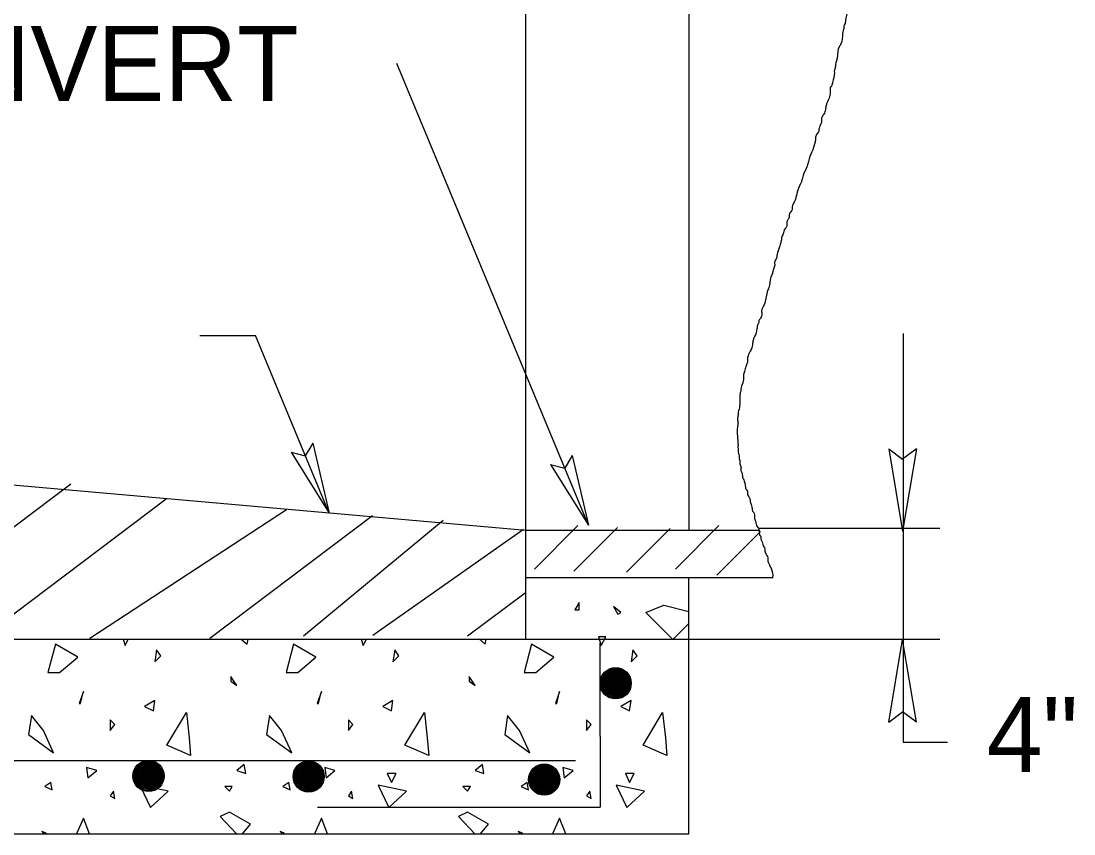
# Model space of a CAD drawing. Extents: x 5.8 to 18, y -5.2 to 5.4.
# Drawn here: x 12.113 to 12.953, y -2.199 to -1.55 of the extents above; entities that cross this region are included whole.
import ezdxf

# ---------------------------------------------------------------- set-up
doc = ezdxf.new("R2010")
doc.units = 0
for name, color, linetype in [('DETL-DIMS', 7, 'Continuous'), ('DETL-LINE', 7, 'Continuous'), ('DETL-NOTE', 7, 'Continuous'), ('DETL-PATT', 7, 'Continuous')]:
    doc.layers.add(name, color=color, linetype=linetype)

msp = doc.modelspace()

# ---------------------------------------------------------------- linework, layer by layer
at = {"layer": 'DETL-DIMS'}
for p, q in [((12.566, -1.95226), (12.41306, -1.58371)), ((12.2558, -1.80088), (12.3002, -1.80088)), ((12.35898, -1.94253), (12.3002, -1.80088)), ((12.81726, -1.7993), (12.81726, -2.12544)), ((12.34604, -1.88677), (12.34004, -1.89688)), ((12.34604, -1.88677), (12.35898, -1.94253)), ((12.32867, -1.89398), (12.35898, -1.94253)), ((12.32867, -1.89398), (12.34004, -1.89688)), ((12.55306, -1.89649), (12.54706, -1.90661)), ((12.55306, -1.89649), (12.566, -1.95226)), ((12.80576, -1.8913), (12.81674, -1.95718)), ((12.80576, -1.8913), (12.81674, -1.89953)), ((12.82772, -1.8913), (12.81674, -1.95718)), ((12.82772, -1.8913), (12.81674, -1.89953)), ((12.53569, -1.90371), (12.566, -1.95226)), ((12.53569, -1.90371), (12.54706, -1.90661)), ((12.70169, -1.95465), (12.84634, -1.95465)), ((12.51612, -2.04328), (12.84634, -2.04328)), ((12.80576, -2.10927), (12.81674, -2.04339)), ((12.82772, -2.10927), (12.81674, -2.04339)), ((12.80576, -2.10927), (12.81674, -2.10103)), ((12.82772, -2.10927), (12.81674, -2.10103)), ((12.81726, -2.12544), (12.85257, -2.12544))]:
    msp.add_line(p, q, dxfattribs=at)
at = {"layer": 'DETL-LINE'}
for p, q in [((12.51612, -2.04328), (12.51612, -0.81414)), ((12.646, -1.47622), (12.646, -1.95618)), ((12.51612, -1.95637), (11.58024, -1.87386)), ((12.51667, -1.95618), (12.70208, -1.95618)), ((12.51639, -1.9939), (12.71329, -1.9939)), ((12.646, -2.19861), (12.646, -1.9939)), ((11.5809, -2.04328), (12.51612, -2.04328)), ((12.57525, -2.12069), (12.57525, -2.04645)), ((12.57525, -2.12069), (12.57525, -2.17712)), ((11.53804, -2.1399), (12.55565, -2.1399)), ((12.34969, -2.17712), (12.57525, -2.17712)), ((11.45961, -2.19861), (12.646, -2.19861))]:
    msp.add_line(p, q, dxfattribs=at)
for centre, radius in [((12.58772, -2.07837), 0.01247), ((12.58761, -2.07827), 0.01163), ((12.5865, -2.07827), 0.01009), ((12.58775, -2.07856), 0.01122), ((12.58808, -2.07909), 0.011), ((12.58803, -2.0787), 0.01024), ((12.58691, -2.07778), 0.00834), ((12.5883, -2.07876), 0.00969), ((12.58838, -2.07903), 0.00918), ((12.58671, -2.07876), 0.00724), ((12.58852, -2.07917), 0.00876), ((12.58838, -2.07939), 0.00835), ((12.58608, -2.07917), 0.00578), ((12.58859, -2.07939), 0.00814), ((12.58844, -2.07925), 0.00786), ((12.58879, -2.07945), 0.00751), ((12.58887, -2.07931), 0.00704), ((12.58705, -2.0789), 0.00467), ((12.58893, -2.07923), 0.00655), ((12.58893, -2.07909), 0.006), ((12.58901, -2.07925), 0.00565), ((12.58901, -2.07931), 0.0051), ((12.58922, -2.07974), 0.00488), ((12.58934, -2.0798), 0.00445), ((12.58934, -2.07968), 0.0039), ((12.5895, -2.07958), 0.00377), ((12.5895, -2.07994), 0.00347), ((12.58963, -2.07966), 0.00333), ((12.58969, -2.07974), 0.00285), ((12.5895, -2.07952), 0.00238), ((12.58977, -2.07982), 0.00212), ((12.58985, -2.0798), 0.00175), ((12.58999, -2.07988), 0.00133), ((12.58999, -2.07974), 0.00118), ((12.5904, -2.0798), 0.00148), ((12.58997, -2.07974), 0.000769), ((12.58983, -2.07974), 0.000362), ((12.59012, -2.07974), 0.00023), ((12.21498, -2.15237), 0.01247), ((12.21487, -2.15227), 0.01163), ((12.21376, -2.15227), 0.01009), ((12.21501, -2.15256), 0.01122), ((12.21534, -2.15309), 0.011), ((12.21529, -2.1527), 0.01024), ((12.34271, -2.15281), 0.01247), ((12.34261, -2.15271), 0.01163), ((12.34275, -2.153), 0.01122), ((12.34308, -2.15353), 0.011), ((12.21417, -2.15178), 0.00834), ((12.21556, -2.15276), 0.00969), ((12.21564, -2.15303), 0.00918), ((12.21397, -2.15276), 0.00724), ((12.21578, -2.15317), 0.00876), ((12.21564, -2.15338), 0.00835), ((12.21334, -2.15317), 0.00578), ((12.21585, -2.15338), 0.00814), ((12.2157, -2.15325), 0.00786), ((12.21605, -2.15344), 0.00751), ((12.21613, -2.1533), 0.00704), ((12.21431, -2.15289), 0.00467), ((12.21619, -2.15323), 0.00655), ((12.21619, -2.15309), 0.006), ((12.21627, -2.15325), 0.00565), ((12.21627, -2.1533), 0.0051), ((12.21648, -2.15374), 0.00488), ((12.2166, -2.15379), 0.00445), ((12.2166, -2.15368), 0.0039), ((12.21676, -2.15358), 0.00377), ((12.21676, -2.15393), 0.00347), ((12.21689, -2.15366), 0.00333), ((12.21695, -2.15374), 0.00285), ((12.34149, -2.15271), 0.01009), ((12.34302, -2.15314), 0.01024), ((12.3419, -2.15222), 0.00834), ((12.34329, -2.1532), 0.00969), ((12.34337, -2.15347), 0.00918), ((12.34171, -2.1532), 0.00724), ((12.34351, -2.15361), 0.00876), ((12.34337, -2.15383), 0.00835), ((12.34108, -2.15361), 0.00578), ((12.34359, -2.15383), 0.00814), ((12.34343, -2.15369), 0.00786), ((12.34378, -2.15388), 0.00751), ((12.34386, -2.15375), 0.00704), ((12.34392, -2.15367), 0.00655), ((12.34204, -2.15334), 0.00467), ((12.34392, -2.15353), 0.006), ((12.344, -2.15369), 0.00565), ((12.344, -2.15375), 0.0051), ((12.34422, -2.15418), 0.00488), ((12.34433, -2.15424), 0.00445), ((12.34433, -2.15412), 0.0039), ((12.34449, -2.15402), 0.00377), ((12.34449, -2.15437), 0.00347), ((12.34463, -2.1541), 0.00333), ((12.53068, -2.15524), 0.01247), ((12.53057, -2.15514), 0.01163), ((12.52945, -2.15514), 0.01009), ((12.53071, -2.15543), 0.01122), ((12.53104, -2.15596), 0.011), ((12.53098, -2.15557), 0.01024), ((12.52986, -2.15465), 0.00834), ((12.53125, -2.15563), 0.00969), ((12.53133, -2.1559), 0.00918), ((12.52967, -2.15563), 0.00724), ((12.53147, -2.15604), 0.00876), ((12.53133, -2.15626), 0.00835), ((12.52904, -2.15604), 0.00578), ((12.53155, -2.15626), 0.00814), ((12.53139, -2.15612), 0.00786), ((12.53175, -2.15632), 0.00751), ((12.53182, -2.15618), 0.00704), ((12.53188, -2.1561), 0.00655), ((12.53188, -2.15596), 0.006), ((12.53196, -2.15612), 0.00565), ((12.21676, -2.15352), 0.00238), ((12.21703, -2.15381), 0.00212), ((12.21711, -2.15379), 0.00175), ((12.21725, -2.15387), 0.00133), ((12.21725, -2.15374), 0.00118), ((12.21766, -2.15379), 0.00148), ((12.21723, -2.15374), 0.000769), ((12.21709, -2.15374), 0.000362), ((12.21738, -2.15374), 0.00023), ((12.34469, -2.15418), 0.00285), ((12.34449, -2.15396), 0.00238), ((12.34476, -2.15426), 0.00212), ((12.34484, -2.15424), 0.00175), ((12.34498, -2.15432), 0.00133), ((12.34498, -2.15418), 0.00118), ((12.34539, -2.15424), 0.00148), ((12.34496, -2.15418), 0.000769), ((12.34482, -2.15418), 0.000362), ((12.34512, -2.15418), 0.00023), ((12.53, -2.15577), 0.00467), ((12.53196, -2.15618), 0.0051), ((12.53218, -2.15661), 0.00488), ((12.53229, -2.15667), 0.00445), ((12.53229, -2.15655), 0.0039), ((12.53245, -2.15645), 0.00377), ((12.53245, -2.15681), 0.00347), ((12.53259, -2.15653), 0.00333), ((12.53265, -2.15661), 0.00285), ((12.53245, -2.15639), 0.00238), ((12.53273, -2.15669), 0.00212), ((12.5328, -2.15667), 0.00175), ((12.53294, -2.15675), 0.00133), ((12.53294, -2.15661), 0.00118), ((12.53335, -2.15667), 0.00148), ((12.53292, -2.15661), 0.000769), ((12.53278, -2.15661), 0.000362), ((12.53308, -2.15661), 0.00023)]:
    msp.add_circle(centre, radius, dxfattribs=at)
msp.add_arc((12.70085, -1.99271), 0.01247, 354.49539, 26.62684, dxfattribs=at)
for points in [[(12.76761, -1.45041), (12.76714, -1.4523), (12.76761, -1.45371), (12.76757, -1.45512), (12.76804, -1.45653), (12.76804, -1.45794), (12.76851, -1.45983), (12.76898, -1.46218), (12.76898, -1.46406), (12.76992, -1.46547), (12.76992, -1.46735), (12.77086, -1.47065), (12.77086, -1.47347), (12.7718, -1.47818), (12.77176, -1.48053), (12.77271, -1.48288), (12.77271, -1.48524), (12.77318, -1.489), (12.77318, -1.49041), (12.77412, -1.49653), (12.77412, -1.5003), (12.77459, -1.50312), (12.77455, -1.51347), (12.77502, -1.51583), (12.77455, -1.51822), (12.77455, -1.52198), (12.77408, -1.52481), (12.77408, -1.53139), (12.77314, -1.53563), (12.77314, -1.53751), (12.77267, -1.53939), (12.77263, -1.54081), (12.77216, -1.54269), (12.77216, -1.5441), (12.77169, -1.54645), (12.77122, -1.54881), (12.77075, -1.55163), (12.7698, -1.55351), (12.7698, -1.55586), (12.76933, -1.55728), (12.76886, -1.55963), (12.76745, -1.5681), (12.76604, -1.57045), (12.76463, -1.57798), (12.76416, -1.58081), (12.76322, -1.5841), (12.76275, -1.58739), (12.76227, -1.58881), (12.76224, -1.59116), (12.76082, -1.59873), (12.75988, -1.60155), (12.75894, -1.60296), (12.75894, -1.60532), (12.75659, -1.61473), (12.75565, -1.61708), (12.75518, -1.62037), (12.75376, -1.62414), (12.75235, -1.62649), (12.75188, -1.62837), (12.75188, -1.63073), (12.75, -1.63543), (12.74953, -1.63826), (12.74765, -1.64108), (12.74718, -1.6439), (12.74671, -1.6472), (12.74431, -1.65426), (12.74149, -1.66179), (12.74055, -1.66555), (12.73725, -1.67308), (12.73631, -1.67688), (12.73537, -1.67924), (12.73443, -1.68112), (12.73302, -1.68488), (12.73161, -1.69053), (12.73067, -1.69335), (12.72878, -1.69712), (12.72831, -1.70088), (12.72643, -1.70371), (12.72596, -1.707), (12.72455, -1.70935), (12.72408, -1.71406), (12.7222, -1.71641), (12.72173, -1.71877), (12.72031, -1.72206), (12.71984, -1.72535), (12.7189, -1.72818), (12.71843, -1.73006), (12.71651, -1.73618), (12.71604, -1.739), (12.71463, -1.74183), (12.71463, -1.74465), (12.71369, -1.74794), (12.71275, -1.75124), (12.71133, -1.75504), (12.71086, -1.75786), (12.70992, -1.76257), (12.70851, -1.76586)], [(12.70851, -1.76586), (12.7071, -1.77339), (12.70616, -1.77622), (12.70522, -1.7781), (12.70427, -1.78045), (12.70427, -1.78328), (12.70333, -1.78704), (12.70192, -1.78892), (12.70192, -1.79034), (12.70098, -1.79269), (12.70047, -1.79551), (12.69859, -1.80163), (12.69765, -1.80351), (12.69718, -1.80539), (12.69671, -1.80916), (12.69435, -1.81481), (12.69294, -1.81951), (12.69294, -1.82234), (12.692, -1.82422), (12.69153, -1.82563), (12.69059, -1.82939), (12.68965, -1.83273), (12.68965, -1.83602), (12.68824, -1.8412), (12.68729, -1.8459), (12.68682, -1.84873), (12.68678, -1.85014), (12.68584, -1.86096), (12.68537, -1.86285), (12.68537, -1.86426), (12.6849, -1.86755), (12.68537, -1.87085), (12.6849, -1.87367), (12.6849, -1.8812), (12.68533, -1.88685), (12.68533, -1.89014), (12.6858, -1.89485), (12.68627, -1.89673), (12.68627, -1.89908), (12.68675, -1.90049), (12.68675, -1.90332), (12.68769, -1.90567), (12.68769, -1.90849), (12.68859, -1.91085), (12.68906, -1.91418), (12.69, -1.91606), (12.69047, -1.91794), (12.69094, -1.91935), (12.69188, -1.92359), (12.69282, -1.925), (12.69282, -1.92641), (12.69329, -1.9283), (12.69467, -1.93112), (12.69514, -1.93347), (12.69561, -1.93488), (12.69655, -1.93865), (12.69702, -1.941), (12.69796, -1.94194), (12.69843, -1.94618), (12.69937, -1.949), (12.69984, -1.95135), (12.70075, -1.95324), (12.70169, -1.95465), (12.70216, -1.95653), (12.7031, -1.96077), (12.70357, -1.96124), (12.70357, -1.96218), (12.70498, -1.96641), (12.70545, -1.96877), (12.70639, -1.97018), (12.70686, -1.97159), (12.70682, -1.973), (12.70729, -1.97441), (12.70918, -1.97818), (12.70918, -1.981), (12.71012, -1.98335), (12.71106, -1.98524), (12.712, -1.98712)]]:
    msp.add_spline(points, degree=3, dxfattribs=at)
at = {"layer": 'DETL-PATT'}
for p, q in [((11.99161, -2.04081), (12.15286, -1.91908)), ((12.08545, -2.03947), (12.22898, -1.93116)), ((12.16808, -2.04241), (12.32506, -1.93975)), ((12.26388, -2.04237), (12.39361, -1.94445)), ((12.33855, -2.04049), (12.44996, -1.94822)), ((12.39396, -2.04002), (12.51427, -1.95528)), ((12.52282, -1.98728), (12.55765, -1.95245)), ((12.55439, -1.98888), (12.58922, -1.95406)), ((12.59647, -1.98971), (12.63129, -1.95488)), ((12.63533, -1.98728), (12.67016, -1.95245)), ((12.66851, -1.99214), (12.70333, -1.95732)), ((12.46957, -2.04049), (12.51561, -2.00614))]:
    msp.add_line(p, q, dxfattribs=at)
for points in [[(12.55851, -2.01375), (12.5551, -2.01967), (12.55851, -2.01967)], [(12.58957, -2.02308), (12.5918, -2.02194), (12.58588, -2.01716)], [(12.57404, -2.04116), (12.57627, -2.04822), (12.57996, -2.04116)], [(12.144, -2.06967), (12.15839, -2.05751), (12.14063, -2.04708), (12.13467, -2.06967)], [(12.33404, -2.06967), (12.34843, -2.05751), (12.33063, -2.04708), (12.32471, -2.06967)], [(12.52404, -2.06967), (12.53843, -2.05751), (12.52067, -2.04708), (12.51475, -2.06967)], [(12.22137, -2.05159), (12.21996, -2.0612), (12.22475, -2.05637)], [(12.41137, -2.05159), (12.40996, -2.0612), (12.41478, -2.05637)], [(12.60141, -2.05159), (12.6, -2.0612), (12.60478, -2.05637)], [(12.28067, -2.07304), (12.28067, -2.07673), (12.28545, -2.0801)], [(12.47067, -2.07304), (12.47067, -2.07673), (12.47549, -2.0801)], [(12.15953, -2.09449), (12.16067, -2.09449), (12.1629, -2.08492)], [(12.21176, -2.09677), (12.21882, -2.10045), (12.21996, -2.09198)], [(12.34957, -2.09449), (12.35067, -2.09449), (12.35294, -2.08492)], [(12.4018, -2.09677), (12.40886, -2.10045), (12.40996, -2.09198)], [(12.53957, -2.09449), (12.54071, -2.09449), (12.54298, -2.08492)], [(12.5918, -2.09677), (12.59886, -2.10045), (12.6, -2.09198)], [(12.12141, -2.1041), (12.11914, -2.11935), (12.13922, -2.13375), (12.13102, -2.11598)], [(12.18439, -2.10751), (12.18439, -2.11598), (12.18804, -2.11116)], [(12.24733, -2.1219), (12.24847, -2.13602), (12.22957, -2.12783), (12.2451, -2.10155)], [(12.31145, -2.1041), (12.30918, -2.11935), (12.32922, -2.13375), (12.32102, -2.11598)], [(12.37439, -2.10751), (12.37439, -2.11598), (12.37808, -2.11116)], [(12.43737, -2.1219), (12.43851, -2.13602), (12.41957, -2.12783), (12.4351, -2.10155)], [(12.50145, -2.1041), (12.49922, -2.11935), (12.51925, -2.13375), (12.51106, -2.11598)], [(12.56443, -2.10751), (12.56443, -2.11598), (12.56808, -2.11116)], [(12.62737, -2.1219), (12.62851, -2.13602), (12.60961, -2.12783), (12.62514, -2.10155)], [(12.16545, -2.14563), (12.16659, -2.15379), (12.17365, -2.14786)], [(12.21545, -2.15041), (12.21882, -2.15747), (12.22251, -2.15041)], [(12.29137, -2.14308), (12.28545, -2.14786), (12.29251, -2.15041)], [(12.35549, -2.14563), (12.35663, -2.15379), (12.36369, -2.14786)], [(12.40545, -2.15041), (12.40886, -2.15747), (12.41251, -2.15041)], [(12.48141, -2.14308), (12.47549, -2.14786), (12.48255, -2.15041)], [(12.54549, -2.14563), (12.54663, -2.15379), (12.55369, -2.14786)], [(12.59549, -2.15041), (12.59886, -2.15747), (12.60255, -2.15041)], [(12.13216, -2.16085), (12.13808, -2.16339), (12.13694, -2.15747)], [(12.32216, -2.16085), (12.32808, -2.16339), (12.32698, -2.15747)], [(12.5122, -2.16085), (12.51812, -2.16339), (12.51698, -2.15747)], [(12.18439, -2.16822), (12.18804, -2.17045), (12.1869, -2.16453)], [(12.20808, -2.15975), (12.21655, -2.17751), (12.23067, -2.16453)], [(12.27584, -2.16085), (12.27953, -2.16453), (12.2818, -2.16085)], [(12.37439, -2.16822), (12.37808, -2.17045), (12.37694, -2.16453)], [(12.39812, -2.15975), (12.40659, -2.17751), (12.42071, -2.16453)], [(12.46588, -2.16085), (12.46957, -2.16453), (12.4718, -2.16085)], [(12.56443, -2.16822), (12.56808, -2.17045), (12.56698, -2.16453)], [(12.58816, -2.15975), (12.59663, -2.17751), (12.61075, -2.16453)]]:
    msp.add_lwpolyline(points, close=True, dxfattribs=at)
for points in [[(12.646, -2.03069), (12.63333, -2.04339), (12.61184, -2.02194), (12.62627, -2.01602), (12.646, -2.02112)], [(12.19467, -2.04328), (12.19624, -2.04822), (12.19878, -2.04328)], [(12.25341, -2.04328), (12.25325, -2.04339), (12.25314, -2.04328)], [(12.28894, -2.04328), (12.29365, -2.04708), (12.29435, -2.04328)], [(12.38467, -2.04328), (12.38627, -2.04822), (12.38882, -2.04328)], [(12.44341, -2.04328), (12.44329, -2.04339), (12.44318, -2.04328)], [(12.47898, -2.04328), (12.48369, -2.04708), (12.48439, -2.04328)], [(12.28984, -2.19861), (12.2962, -2.19081), (12.27953, -2.1812), (12.2722, -2.18457), (12.28525, -2.19861)], [(12.47988, -2.19861), (12.4862, -2.19081), (12.46957, -2.1812), (12.4622, -2.18457), (12.47529, -2.19861)], [(12.1678, -2.19861), (12.1629, -2.18598), (12.15737, -2.19861)], [(12.3578, -2.19861), (12.35294, -2.18598), (12.34741, -2.19861)], [(12.54784, -2.19861), (12.54298, -2.18598), (12.53741, -2.19861)], [(12.13325, -2.19861), (12.13325, -2.19786), (12.12988, -2.19673), (12.13176, -2.19861)], [(12.32329, -2.19861), (12.32329, -2.19786), (12.31992, -2.19673), (12.3218, -2.19861)], [(12.51333, -2.19861), (12.51333, -2.19786), (12.50992, -2.19673), (12.5118, -2.19861)]]:
    msp.add_lwpolyline(points, dxfattribs=at)

# ---------------------------------------------------------------- texts
at = {"layer": 'DETL-NOTE'}
for s, p in [('INVERT', (12.04039, -1.61371)), ('4"', (12.88373, -2.14921))]:
    msp.add_text(s, height=0.06, dxfattribs=at).set_placement(p)

doc.saveas('drawing.dxf')
